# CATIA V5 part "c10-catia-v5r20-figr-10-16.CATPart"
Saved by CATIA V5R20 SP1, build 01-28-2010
Part number: Part1
Bounding box of the stored display mesh (mm): x -29.811 to 29.811, y 0 to 29.811, z -21.213 to 21.213
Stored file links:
  D:\v5_r20\psrt_files_downloaded\c10\c10-catia-v5r20-figr-10-16.CATPart
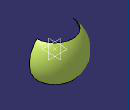
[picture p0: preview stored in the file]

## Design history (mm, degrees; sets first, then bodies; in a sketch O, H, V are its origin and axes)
Set1
  Point1: (0, 0, 0)
  Sphere1: Center Point1, Radius 30, Para1 -45, Para3 0, Para4 180
Body1 (main body)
